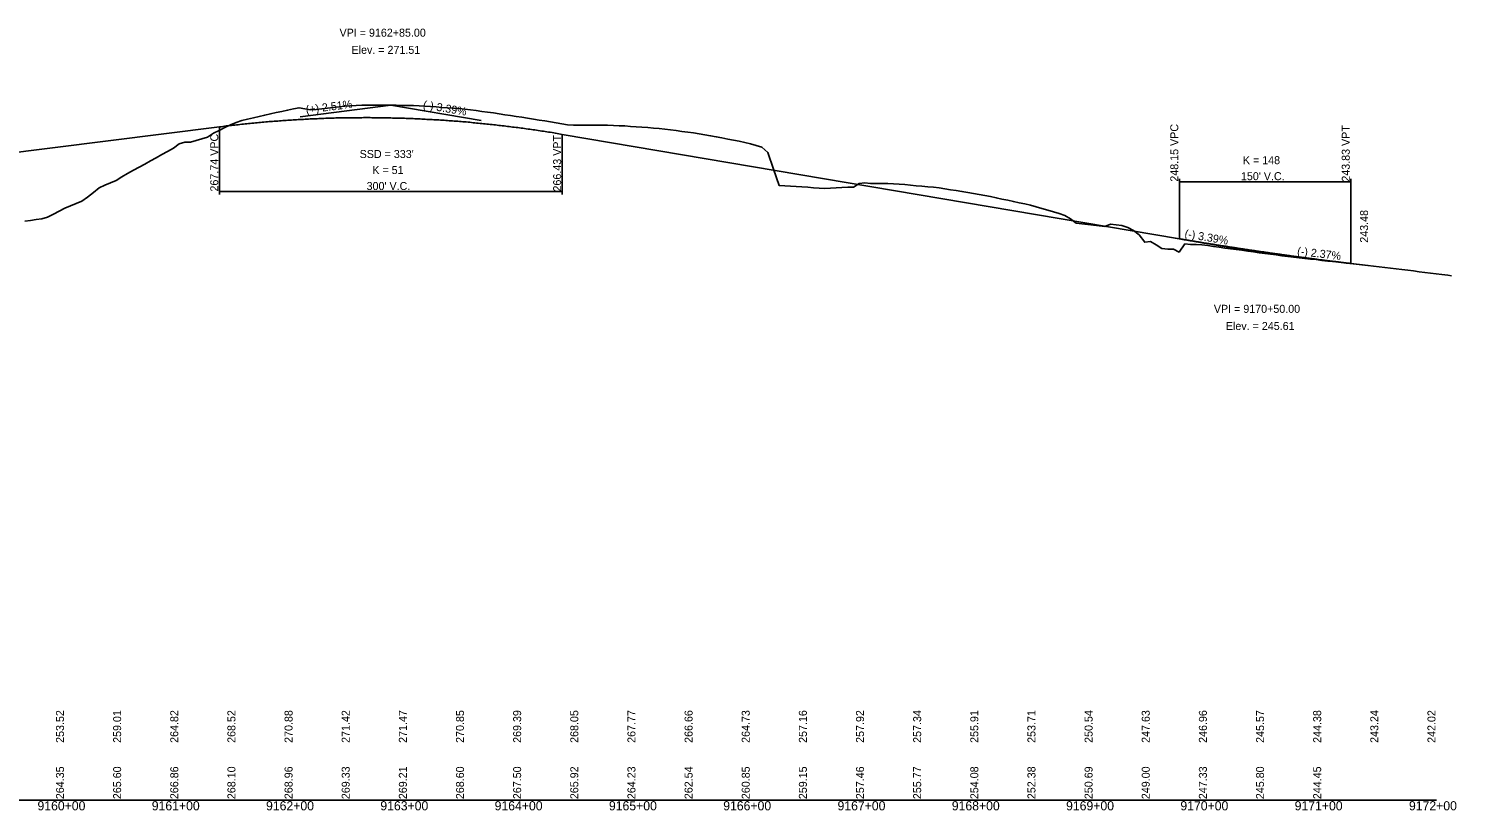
# Model space of a CAD drawing. Extents: x 1838386 to 1955906, y 719739 to 834437.
# Drawn here: x 1898150 to 1899399, y 743480 to 744164 of the extents above; entities that cross this region are included whole.
import ezdxf

# ---------------------------------------------------------------- set-up
doc = ezdxf.new("R2010")
doc.units = 0
for name, color, linetype in [('RD_DDB_GradeTX', 7, 'Continuous'), ('RD_DDB_Profile_EX', 7, 'Continuous'), ('RD_DDB_Profile_Lbl', 7, 'Continuous'), ('RD_DDB_Profile_PR', 7, 'Continuous'), ('RD_DDB_StaTX', 7, 'Continuous'), ('RD_DDB_StripGrade', 7, 'Continuous'), ('RD_DDB_VCLbl', 7, 'Continuous'), ('RD_GPK_Profile_Cell', 7, 'Continuous')]:
    doc.layers.add(name, color=color, linetype=linetype)

msp = doc.modelspace()

# ---------------------------------------------------------------- linework, layer by layer
at = {"layer": 'RD_DDB_GradeTX'}
for p, q in [((1898387.2, 744086.7), (1898466.6, 744096.7)), ((1898545.5, 744083.3), (1898466.6, 744096.7)), ((1899152.7, 743980.6), (1899231.6, 743967.2)), ((1899311.1, 743957.8), (1899231.6, 743967.2))]:
    msp.add_line(p, q, dxfattribs=at)
at = {"layer": 'RD_DDB_Profile_EX'}
for points in [[(1898146.3, 743995.3), (1898151.3, 743996), (1898156.3, 743996.7), (1898161.3, 743997.4), (1898166.3, 743998.8), (1898171.3, 744001.4), (1898176.3, 744004.1), (1898181.3, 744006.6), (1898186.3, 744008.8), (1898191.3, 744010.9), (1898196.3, 744013), (1898201.3, 744016.4), (1898206.3, 744020.5), (1898211.3, 744024.6), (1898216.3, 744026.8), (1898221.3, 744028.9), (1898226.3, 744031), (1898231.3, 744034), (1898236.3, 744037.1), (1898241.3, 744040), (1898246.3, 744042.6), (1898251.3, 744045.3), (1898256.3, 744048), (1898261.3, 744050.8), (1898266.3, 744053.7), (1898271.3, 744056.4), (1898276.3, 744059.2), (1898281.3, 744063.1), (1898286.3, 744064.4), (1898291.3, 744064.4), (1898296.3, 744065.9), (1898301.3, 744067.4), (1898306.3, 744068.9), (1898311.3, 744072.4), (1898316.3, 744074.8), (1898321.3, 744077.3), (1898326.3, 744079.5), (1898331.3, 744081.6), (1898336.3, 744083.3), (1898341.3, 744084.5), (1898346.3, 744085.7), (1898351.3, 744086.9), (1898356.3, 744088.1), (1898361.3, 744089.2), (1898366.3, 744090.3), (1898371.3, 744091.4), (1898376.3, 744092.4), (1898381.3, 744093.5), (1898386.3, 744094.5), (1898391.3, 744093.7), (1898396.3, 744092.6), (1898401.3, 744093.1), (1898406.3, 744093.7), (1898411.3, 744094.3), (1898416.3, 744094.8), (1898421.3, 744095.3), (1898426.3, 744095.8), (1898431.3, 744096.2), (1898436.3, 744096.6), (1898441.3, 744096.8), (1898446.3, 744096.8), (1898451.3, 744096.9), (1898456.3, 744096.9), (1898461.3, 744096.8), (1898466.3, 744096.8), (1898471.3, 744096.7), (1898476.3, 744096.6), (1898481.3, 744096.5), (1898486.3, 744096.4), (1898491.3, 744096.1), (1898496.3, 744095.8), (1898501.3, 744095.6), (1898506.3, 744095.3), (1898511.3, 744094.9), (1898516.3, 744094.6), (1898521.3, 744094.2), (1898526.3, 744093.8), (1898531.3, 744093.4), (1898536.3, 744092.8), (1898541.3, 744092.1), (1898546.3, 744091.4), (1898551.3, 744090.7), (1898556.3, 744090), (1898561.3, 744089.2), (1898566.3, 744088.5), (1898571.3, 744087.7), (1898576.3, 744086.9), (1898581.3, 744086.2), (1898586.3, 744085.4), (1898591.3, 744084.6), (1898596.3, 744083.8), (1898601.3, 744083), (1898606.3, 744082.1), (1898611.3, 744081.3), (1898616.3, 744080.4), (1898621.3, 744079.5), (1898626.3, 744079.3), (1898631.3, 744079.4), (1898636.3, 744079.4), (1898641.3, 744079.4)], [(1898641.3, 744079.4), (1898646.3, 744079.4), (1898651.3, 744079.3), (1898656.3, 744079.2), (1898661.3, 744079), (1898666.3, 744078.8), (1898671.3, 744078.6), (1898676.3, 744078.3), (1898681.3, 744078), (1898686.3, 744077.6), (1898691.3, 744077.2), (1898696.3, 744076.8), (1898701.3, 744076.3), (1898706.3, 744075.8), (1898711.3, 744075.2), (1898716.3, 744074.6), (1898721.3, 744073.9), (1898726.3, 744073.2), (1898731.3, 744072.5), (1898736.3, 744071.7), (1898741.3, 744070.9), (1898746.3, 744070.1), (1898751.3, 744069.2), (1898756.3, 744068.2), (1898761.3, 744067.2), (1898766.3, 744066.2), (1898771.3, 744065.2), (1898776.3, 744064.1), (1898781.3, 744062.9), (1898786.3, 744061.5), (1898791.3, 744060.1), (1898796.3, 744055.4), (1898801.3, 744040.9), (1898806.3, 744026.7), (1898811.3, 744026.4), (1898816.3, 744026), (1898821.3, 744025.6), (1898826.3, 744025.3), (1898831.3, 744025), (1898836.3, 744024.6), (1898841.3, 744024.3), (1898846.3, 744024), (1898851.3, 744024.2), (1898856.3, 744024.5), (1898861.3, 744024.8), (1898866.3, 744025), (1898871.3, 744025.2), (1898876.3, 744028.2), (1898881.3, 744028.8), (1898886.3, 744028.4), (1898891.3, 744028.4), (1898896.3, 744028.4), (1898901.3, 744028.3), (1898906.3, 744028.1), (1898911.3, 744027.7), (1898916.3, 744027.3), (1898921.3, 744026.8), (1898926.3, 744026.3), (1898931.3, 744025.9), (1898936.3, 744025.5), (1898941.3, 744025), (1898946.3, 744024.4), (1898951.3, 744023.7), (1898956.3, 744022.9), (1898961.3, 744022.2), (1898966.3, 744021.4), (1898971.3, 744020.5), (1898976.3, 744019.7), (1898981.3, 744018.8), (1898986.3, 744017.8), (1898991.3, 744016.8), (1898996.3, 744015.8), (1899001.3, 744014.7), (1899006.3, 744013.6), (1899011.3, 744012.5), (1899016.3, 744011.5), (1899021.3, 744010.4), (1899026.3, 744009.3), (1899031.3, 744007.8), (1899036.3, 744006.4), (1899041.3, 744005), (1899046.3, 744003.6), (1899051.3, 744002.1), (1899056.3, 744000.3), (1899061.3, 743997.3), (1899066.3, 743993.7), (1899071.3, 743993.1), (1899076.3, 743992.5), (1899081.3, 743991.9), (1899086.3, 743991.3), (1899091.3, 743990.7), (1899096.3, 743992.6), (1899101.3, 743992.1), (1899106.3, 743991.6), (1899111.3, 743989.7), (1899116.3, 743987.3), (1899121.3, 743983.5), (1899126.3, 743976.9), (1899131.3, 743977.5), (1899136.3, 743974.6), (1899141.3, 743971.5)], [(1899141.3, 743971.5), (1899146.3, 743971), (1899151.3, 743970.8), (1899156.3, 743968.4), (1899161.3, 743975.5), (1899166.3, 743975), (1899171.3, 743974.9), (1899176.3, 743974.7), (1899181.3, 743974), (1899186.3, 743973.2), (1899191.3, 743972.5), (1899196.3, 743971.8), (1899201.3, 743971.1), (1899206.3, 743970.5), (1899211.3, 743970), (1899216.3, 743969.2), (1899221.3, 743968.5), (1899226.3, 743967.7), (1899231.3, 743967), (1899236.3, 743966.4), (1899241.3, 743965.8), (1899246.3, 743965.1), (1899251.3, 743964.5), (1899256.3, 743963.9), (1899261.3, 743963.3), (1899266.3, 743962.8), (1899271.3, 743962.2), (1899276.3, 743961.7), (1899281.3, 743961.1), (1899286.3, 743960.5), (1899291.3, 743960), (1899296.3, 743959.4), (1899301.3, 743958.9), (1899306.3, 743958.3), (1899311.3, 743957.7), (1899316.3, 743957.2), (1899321.3, 743956.6), (1899326.3, 743956), (1899331.3, 743955.4), (1899336.3, 743954.8), (1899341.3, 743954.2), (1899346.3, 743953.6), (1899351.3, 743953), (1899356.3, 743952.4), (1899361.3, 743951.8), (1899366.3, 743951.2), (1899371.3, 743950.5), (1899376.3, 743949.9), (1899381.3, 743949.3), (1899386.3, 743948.7), (1899391.3, 743948.1), (1899394.6, 743947.7)]]:
    msp.add_lwpolyline(points, dxfattribs=at)
at = {"layer": 'RD_DDB_Profile_PR'}
for p, q in [((1897896.6, 744025.1), (1898316.6, 744077.8)), ((1898616.6, 744071.3), (1899156.6, 743979.9)), ((1899306.6, 743958.3), (1899321.6, 743956.5))]:
    msp.add_line(p, q, dxfattribs=at)
for points in [[(1898316.6, 744077.8), (1898322.6, 744078.6), (1898328.6, 744079.3), (1898334.6, 744079.9), (1898340.6, 744080.6), (1898346.6, 744081.2), (1898352.6, 744081.7), (1898358.6, 744082.3), (1898364.6, 744082.7), (1898370.6, 744083.2), (1898376.6, 744083.6), (1898382.6, 744084), (1898388.6, 744084.3), (1898394.6, 744084.7), (1898400.6, 744084.9), (1898406.6, 744085.2), (1898412.6, 744085.4), (1898418.6, 744085.6), (1898424.6, 744085.7), (1898430.6, 744085.8), (1898436.6, 744085.8), (1898442.6, 744085.9), (1898448.6, 744085.9), (1898454.6, 744085.8), (1898460.6, 744085.7), (1898466.6, 744085.6), (1898472.6, 744085.5), (1898478.6, 744085.3), (1898484.6, 744085.1), (1898490.6, 744084.8), (1898496.6, 744084.5), (1898502.6, 744084.2), (1898508.6, 744083.9), (1898514.6, 744083.5), (1898520.6, 744083), (1898526.6, 744082.6), (1898532.6, 744082.1), (1898538.6, 744081.5), (1898544.6, 744080.9), (1898550.6, 744080.3), (1898556.6, 744079.7), (1898562.6, 744079), (1898568.6, 744078.3), (1898574.6, 744077.5), (1898580.6, 744076.8), (1898586.6, 744075.9), (1898592.6, 744075.1), (1898598.6, 744074.2), (1898604.6, 744073.3), (1898610.6, 744072.3), (1898616.6, 744071.3)], [(1899156.6, 743979.9), (1899159.6, 743979.4), (1899162.6, 743978.9), (1899165.6, 743978.4), (1899168.6, 743977.9), (1899171.6, 743977.4), (1899174.6, 743976.9), (1899177.6, 743976.4), (1899180.6, 743975.9), (1899183.6, 743975.5), (1899186.6, 743975), (1899189.6, 743974.5), (1899192.6, 743974), (1899195.6, 743973.6), (1899198.6, 743973.1), (1899201.6, 743972.6), (1899204.6, 743972.2), (1899207.6, 743971.7), (1899210.6, 743971.3), (1899213.6, 743970.8), (1899216.6, 743970.4), (1899219.6, 743969.9), (1899222.6, 743969.5), (1899225.6, 743969), (1899228.6, 743968.6), (1899231.6, 743968.2), (1899234.6, 743967.7), (1899237.6, 743967.3), (1899240.6, 743966.9), (1899243.6, 743966.5), (1899246.6, 743966), (1899249.6, 743965.6), (1899252.6, 743965.2), (1899255.6, 743964.8), (1899258.6, 743964.4), (1899261.6, 743964), (1899264.6, 743963.6), (1899267.6, 743963.2), (1899270.6, 743962.8), (1899273.6, 743962.4), (1899276.6, 743962), (1899279.6, 743961.6), (1899282.6, 743961.3), (1899285.6, 743960.9), (1899288.6, 743960.5), (1899291.6, 743960.1), (1899294.6, 743959.8), (1899297.6, 743959.4), (1899300.6, 743959), (1899303.6, 743958.7), (1899306.6, 743958.3)]]:
    msp.add_spline(points, degree=3, dxfattribs=at)
at = {"layer": 'RD_DDB_VCLbl'}
for p, q in [((1898316.6, 744018.8), (1898316.6, 744077.8)), ((1898616.6, 744018.8), (1898616.6, 744071.3)), ((1899156.6, 744032.4), (1899156.6, 743979.9)), ((1899156.6, 744029.9), (1899306.6, 744029.9)), ((1899306.6, 744032.4), (1899306.6, 743958.3)), ((1898316.6, 744021.3), (1898616.6, 744021.3))]:
    msp.add_line(p, q, dxfattribs=at)
at = {"layer": 'RD_GPK_Profile_Cell'}
msp.add_line((1895681.6, 743489.1), (1899381.6, 743489.1), dxfattribs=at)

# ---------------------------------------------------------------- texts
at = {"layer": 'RD_DDB_GradeTX'}
for s, rotation, p in [('(+) 2.51%', 7.1631, (1898392.6, 744089.4)), ('(-) 3.39%', 350.3928, (1898494.3, 744094)), ('(-) 3.39%', 350.3928, (1899160.7, 743981.2)), ('(-) 2.37%', 353.2396, (1899259.3, 743965.9))]:
    msp.add_text(s, height=7, rotation=rotation, dxfattribs=at).set_placement(p)
at = {"layer": 'RD_DDB_Profile_Lbl'}
for s, p in [('VPI = 9162+85.00', (1898421.7, 744156.7)), ('Elev. = 271.51', (1898432.2, 744141.7)), ('VPI = 9170+50.00', (1899186.7, 743915.2)), ('Elev. = 245.61', (1899197.2, 743900.2))]:
    msp.add_text(s, height=7, dxfattribs=at).set_placement(p)
msp.add_text('243.48', height=7, rotation=90, dxfattribs=at).set_placement((1899321.6, 743976.5))
at = {"layer": 'RD_DDB_StaTX'}
for s, p in [('9160+00', (1898157.4, 743480.1)), ('9161+00', (1898257.4, 743480.1)), ('9162+00', (1898357.4, 743480.1)), ('9163+00', (1898457.4, 743480.1)), ('9164+00', (1898557.4, 743480.1)), ('9165+00', (1898657.4, 743480.1)), ('9166+00', (1898757.4, 743480.1)), ('9167+00', (1898857.4, 743480.1)), ('9168+00', (1898957.4, 743480.1)), ('9169+00', (1899057.4, 743480.1)), ('9170+00', (1899157.4, 743480.1)), ('9171+00', (1899257.4, 743480.1)), ('9172+00', (1899357.4, 743480.1))]:
    msp.add_text(s, height=8, dxfattribs=at).set_placement(p)
at = {"layer": 'RD_DDB_StripGrade'}
for s, p in [('248.15 VPC', (1899155.6, 744029.9)), ('243.83 VPT', (1899305.6, 744029.9)), ('267.74 VPC', (1898315.6, 744021.3)), ('266.43 VPT', (1898615.6, 744021.3)), ('253.52', (1898180.6, 743539.1)), ('259.01', (1898230.6, 743539.1)), ('264.82', (1898280.6, 743539.1)), ('268.52', (1898330.6, 743539.1)), ('270.88', (1898380.6, 743539.1)), ('271.42', (1898430.6, 743539.1)), ('271.47', (1898480.6, 743539.1)), ('270.85', (1898530.6, 743539.1)), ('269.39', (1898580.6, 743539.1)), ('268.05', (1898630.6, 743539.1)), ('267.77', (1898680.6, 743539.1)), ('266.66', (1898730.6, 743539.1)), ('264.73', (1898780.6, 743539.1)), ('257.16', (1898830.6, 743539.1)), ('257.92', (1898880.6, 743539.1)), ('257.34', (1898930.6, 743539.1)), ('255.91', (1898980.6, 743539.1)), ('253.71', (1899030.6, 743539.1)), ('250.54', (1899080.6, 743539.1)), ('247.63', (1899130.6, 743539.1)), ('246.96', (1899180.6, 743539.1)), ('245.57', (1899230.6, 743539.1)), ('244.38', (1899280.6, 743539.1)), ('243.24', (1899330.6, 743539.1)), ('242.02', (1899380.6, 743539.1)), ('264.35', (1898180.6, 743489.9)), ('265.60', (1898230.6, 743489.9)), ('266.86', (1898280.6, 743489.9)), ('268.10', (1898330.6, 743489.9)), ('268.96', (1898380.6, 743489.9)), ('269.33', (1898430.6, 743489.9)), ('269.21', (1898480.6, 743489.9)), ('268.60', (1898530.6, 743489.9)), ('267.50', (1898580.6, 743489.9)), ('265.92', (1898630.6, 743489.9)), ('264.23', (1898680.6, 743489.9)), ('262.54', (1898730.6, 743489.9)), ('260.85', (1898780.6, 743489.9)), ('259.15', (1898830.6, 743489.9)), ('257.46', (1898880.6, 743489.9)), ('255.77', (1898930.6, 743489.9)), ('254.08', (1898980.6, 743489.9)), ('252.38', (1899030.6, 743489.9)), ('250.69', (1899080.6, 743489.9)), ('249.00', (1899130.6, 743489.9)), ('247.33', (1899180.6, 743489.9)), ('245.80', (1899230.6, 743489.9)), ('244.45', (1899280.6, 743489.9))]:
    msp.add_text(s, height=7, rotation=90, dxfattribs=at).set_placement(p)
at = {"layer": 'RD_DDB_VCLbl'}
for s, p in [("SSD = 333'", (1898439.3, 744050.6)), ('K = 148', (1899212.1, 744045.2)), ('K = 51', (1898450.4, 744036.6)), ("150' V.C.", (1899210.4, 744031.2)), ("300' V.C.", (1898445.4, 744022.6))]:
    msp.add_text(s, height=7, dxfattribs=at).set_placement(p)

doc.saveas('drawing.dxf')
